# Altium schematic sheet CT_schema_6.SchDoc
size 254 x 245 mm
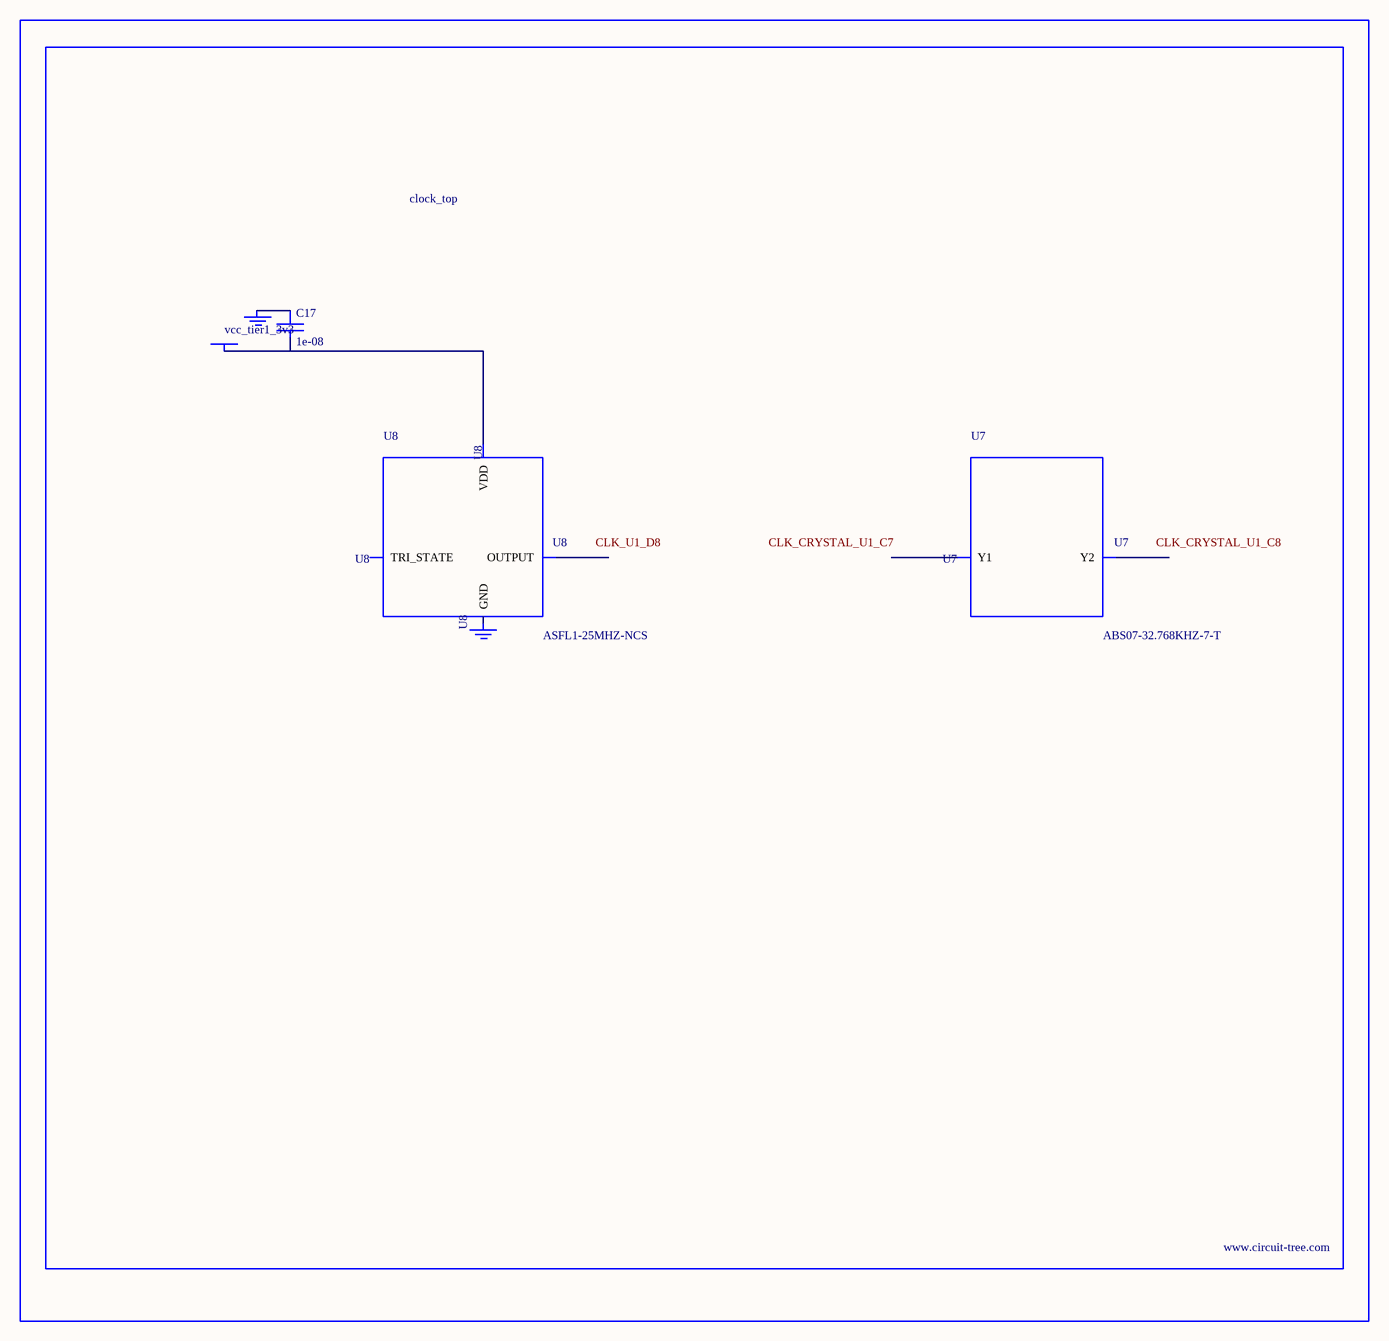
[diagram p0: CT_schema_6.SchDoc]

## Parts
BORDER5  (no value)
C17  1e-08  [C0402]
GND_INSTANCE_5_0  (no value)
GND_INSTANCE_5_1  (no value)
POWER_INSTANCE_5_0  vcc_tier1_3v3
U7  ABS07-32.768KHZ-7-T  [ABS07-32.768KHZ-7-T]
U8  ASFL1-25MHZ-NCS  [ASFL1]

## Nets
NetC17_1: C17.1 GND_INSTANCE_5_0.0(GND)
NetC17_2: C17.2 POWER_INSTANCE_5_0.0(PWR) U8.4(VDD)

Not connected (* = marked no-connect by the designer): GND_INSTANCE_5_1 0(GND); U7 1(Y1) 2(Y2); U8 1(TRI_STATE) 2(GND) 3(OUTPUT)

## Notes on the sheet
- Labels drawn without touching a wire or pin: CLK_CRYSTAL_U1_C7, CLK_CRYSTAL_U1_C8, CLK_U1_D8

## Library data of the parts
BORDER5 = BORDER_PAGE5
C17 = C0402C103K3RAC
GND_INSTANCE_5_0 GND_INSTANCE_5_1 = GND
POWER_INSTANCE_5_0 = PWR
